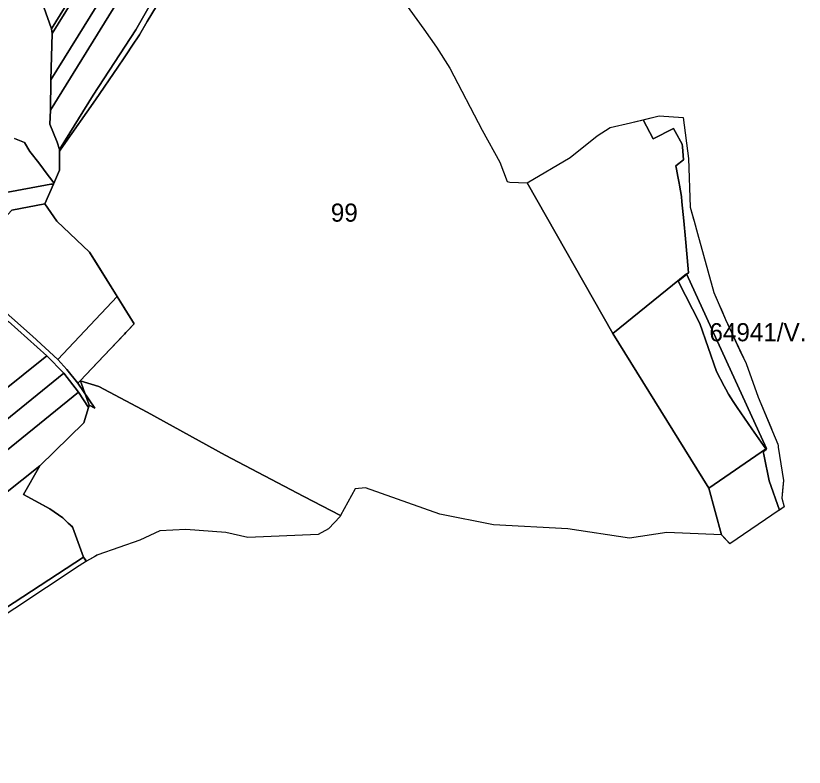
# Model space of a CAD drawing. Extents: x -521939 to -516426, y -1197857 to -1189551.
# Drawn here: x -517973 to -517320, y -1192725 to -1192103 of the extents above; entities that cross this region are included whole.
import ezdxf

# ---------------------------------------------------------------- set-up
doc = ezdxf.new("R2010")
doc.units = 0
for name, color, linetype in [('95610013', 7, 'Continuous'), ('95620013', 7, 'Continuous'), ('95640013', 7, 'Continuous'), ('95660013', 7, 'Continuous')]:
    doc.layers.add(name, color=color, linetype=linetype)

msp = doc.modelspace()

# ---------------------------------------------------------------- linework, layer by layer
at = {"layer": '95610013'}
for points in [[(-517855.24, -1191943.37), (-517837.87, -1191943.45), (-517848.22, -1191960.2), (-517943.23, -1192113.96), (-517949.43, -1192095.84)], [(-517944.02, -1192181.14), (-517850.97, -1192030.5), (-517797.36, -1191943.71), (-517762.7, -1191942.88), (-517770.79, -1191949.6), (-517801.09, -1191977.67), (-517817.56, -1192011.96), (-517823.62, -1192029.85), (-517844.83, -1192064.77), (-517873.31, -1192114.59), (-517908.65, -1192168.84), (-517936.59, -1192213.7), (-517938.51, -1192207.57), (-517944.58, -1192192.89)], [(-517797.36, -1191943.71), (-517850.97, -1192030.5), (-517944.02, -1192181.14), (-517943.62, -1192156.22), (-517849.72, -1192004.37), (-517812.16, -1191943.63)], [(-517834.43, -1191943.43), (-517812.16, -1191943.63), (-517849.72, -1192004.37), (-517943.62, -1192156.22), (-517942.72, -1192117.68), (-517847.17, -1191963.93)], [(-517943.23, -1192113.96), (-517848.22, -1191960.2), (-517837.87, -1191943.45), (-517834.43, -1191943.43), (-517847.17, -1191963.93), (-517942.72, -1192117.68)], [(-517888.81, -1192335.51), (-517938.01, -1192387.6), (-517958.84, -1192368.12), (-518010.6, -1192322.82), (-518012.03, -1192297.79), (-517998.31, -1192288.04), (-517976.01, -1192263.94), (-517948.58, -1192258.68), (-517938.71, -1192273.08), (-517911.8, -1192298.65)], [(-517938.01, -1192387.6), (-517888.81, -1192335.51), (-517874.81, -1192357.96), (-517919.33, -1192405.1), (-517921.42, -1192407.14), (-517930.4, -1192395.85)], [(-517979.17, -1192355.85), (-517947.12, -1192384.46), (-518062.13, -1192476.65), (-518198.61, -1192586.05), (-518210.9, -1192543.36), (-518070.51, -1192429.76)], [(-517947.12, -1192384.46), (-517933.09, -1192398.78), (-518052.55, -1192495.67), (-518192.07, -1192608.83), (-518198.61, -1192586.05), (-518062.13, -1192476.65)], [(-518192.07, -1192608.83), (-518052.55, -1192495.67), (-517933.09, -1192398.78), (-517920.9, -1192414.69), (-518047.2, -1192516.99), (-518186.13, -1192629.52)], [(-517920.9, -1192414.69), (-517912.56, -1192427.26), (-517916.41, -1192439.93), (-517952.89, -1192475.46), (-518042.44, -1192546.79), (-518178.78, -1192655.39), (-518186.13, -1192629.52), (-518047.2, -1192516.99)], [(-518178.78, -1192655.39), (-518042.44, -1192546.79), (-517952.89, -1192475.46), (-517966.33, -1192499.14), (-517944.59, -1192511.06), (-517933.87, -1192518.63), (-517925.61, -1192526.94), (-517916.64, -1192551.13), (-518003.1, -1192607.37), (-518073.65, -1192666.41), (-518085.13, -1192672.38), (-518111.4, -1192679.81), (-518157.63, -1192713.61), (-518162.65, -1192711.95)]]:
    msp.add_lwpolyline(points, close=True, dxfattribs=at)
at = {"layer": '95620013'}
msp.add_lwpolyline([(-517656.03, -1192084.87), (-517635, -1192114.23), (-517624.42, -1192129.01), (-517613.53, -1192146.34), (-517586.8, -1192197.68), (-517571.95, -1192224.17), (-517565.87, -1192240.11), (-517563.82, -1192240.76), (-517549.32, -1192241.33), (-517478.65, -1192365.95), (-517398.96, -1192494.02), (-517388.6, -1192532.69), (-517433.84, -1192530.84), (-517464.79, -1192535.46), (-517515.88, -1192527.65), (-517577.37, -1192524.4), (-517621.73, -1192515.48), (-517683.24, -1192493.66), (-517691.85, -1192494.5), (-517703.94, -1192516.77), (-517734.25, -1192500.81), (-517799.3, -1192466.75), (-517863.9, -1192431.15), (-517904.01, -1192409.83), (-517919.33, -1192405.1), (-517874.81, -1192357.96), (-517888.81, -1192335.51), (-517911.8, -1192298.65), (-517938.71, -1192273.08), (-517948.58, -1192258.68), (-517941.62, -1192242.33), (-517936.68, -1192230.73), (-517936.59, -1192213.7), (-517908.65, -1192168.84), (-517873.31, -1192114.59), (-517844.83, -1192064.77)], dxfattribs=at)
for points in [[(-517381.57, -1192539.95), (-517388.6, -1192532.69), (-517398.96, -1192494.02), (-517351.35, -1192461.17), (-517417.53, -1192316.62), (-517478.65, -1192365.95), (-517549.32, -1192241.33), (-517513.77, -1192220.34), (-517491.36, -1192202.35), (-517480.7, -1192195.55), (-517463.82, -1192191.59), (-517440.05, -1192185.9), (-517420.36, -1192187.14), (-517415.92, -1192221.1), (-517414.44, -1192261.44), (-517411.2, -1192273.11), (-517408.37, -1192283.3), (-517394.85, -1192332.07), (-517385.15, -1192354.39), (-517368.25, -1192390.88), (-517358.3, -1192418.72), (-517346.37, -1192447.19), (-517342.01, -1192457.6), (-517341.78, -1192459.09), (-517341.63, -1192460.06), (-517337.35, -1192487.59), (-517338.56, -1192502.18), (-517336.77, -1192509.6), (-517340.8, -1192512.33)], [(-517351.35, -1192461.17), (-517398.96, -1192494.02), (-517478.65, -1192365.95), (-517417.53, -1192316.62)], [(-517780.59, -1192534.85), (-517798.9, -1192530.79), (-517831.88, -1192528.24), (-517853.37, -1192529.23), (-517870.09, -1192537.11), (-517904.9, -1192549.16), (-517914.33, -1192554.36), (-517916.64, -1192551.13), (-517925.61, -1192526.94), (-517933.87, -1192518.63), (-517944.59, -1192511.06), (-517966.33, -1192499.14), (-517952.89, -1192475.46), (-517916.41, -1192439.93), (-517912.56, -1192427.26), (-517911.95, -1192425.26), (-517907.44, -1192427.78), (-517921.42, -1192407.14), (-517919.33, -1192405.1), (-517904.01, -1192409.83), (-517863.9, -1192431.15), (-517799.3, -1192466.75), (-517734.25, -1192500.81), (-517703.94, -1192516.77), (-517704.26, -1192517.36), (-517713.94, -1192527.65), (-517722.38, -1192532.36)]]:
    msp.add_lwpolyline(points, close=True, dxfattribs=at)
at = {"layer": '95640013'}
for points in [[(-517949.43, -1192095.84), (-517943.23, -1192113.96), (-517942.72, -1192117.68), (-517943.62, -1192156.22), (-517944.02, -1192181.14), (-517944.58, -1192192.89), (-517938.51, -1192207.57), (-517936.59, -1192213.7), (-517936.68, -1192230.73), (-517941.62, -1192242.33), (-517943.65, -1192242.55), (-517983.84, -1192249.8)], [(-517983.84, -1192249.8), (-517943.65, -1192242.55), (-517941.62, -1192242.33), (-517948.58, -1192258.68), (-517976.01, -1192263.94)], [(-518010.6, -1192322.82), (-517958.84, -1192368.12), (-517938.01, -1192387.6), (-517930.4, -1192395.85), (-517921.42, -1192407.14), (-517907.44, -1192427.78), (-517911.95, -1192425.26), (-517912.56, -1192427.26), (-517920.9, -1192414.69), (-517933.09, -1192398.78), (-517947.12, -1192384.46), (-517979.17, -1192355.85)]]:
    msp.add_lwpolyline(points, dxfattribs=at)
msp.add_lwpolyline([(-517914.33, -1192554.36), (-517920.39, -1192558.37), (-518000.71, -1192611.51), (-518044.98, -1192646.87), (-518100.15, -1192695.18), (-518106.7, -1192687.4), (-518113.39, -1192685.66), (-518137.16, -1192707.07), (-518143.03, -1192712.13), (-518149.04, -1192717.31), (-518158.94, -1192724.96), (-518162.65, -1192711.95), (-518157.63, -1192713.61), (-518111.4, -1192679.81), (-518085.13, -1192672.38), (-518073.65, -1192666.41), (-518003.1, -1192607.37), (-517916.64, -1192551.13)], close=True, dxfattribs=at)
at = {"layer": '95660013'}
for points in [[(-517852.5, -1192088.57), (-517863.87, -1192107.85), (-517870.31, -1192118.76), (-517872.65, -1192122.28), (-517874.38, -1192124.89), (-517882.99, -1192137.84), (-517888.28, -1192145.57), (-517906.87, -1192172.76), (-517933.46, -1192210.67), (-517936.6, -1192215.11), (-517936.59, -1192213.7), (-517938.51, -1192207.57), (-517944.58, -1192192.89), (-517944.02, -1192181.14), (-517943.62, -1192156.22), (-517942.72, -1192117.68), (-517943.23, -1192113.96), (-517949.43, -1192095.84)], [(-517949.43, -1192095.84), (-517943.23, -1192113.96), (-517942.72, -1192117.68), (-517943.62, -1192156.22), (-517944.02, -1192181.14), (-517944.58, -1192192.89), (-517938.51, -1192207.57), (-517936.59, -1192213.7), (-517936.6, -1192215.11), (-517933.46, -1192210.67), (-517906.87, -1192172.76), (-517888.28, -1192145.57), (-517882.99, -1192137.84), (-517874.38, -1192124.89), (-517872.65, -1192122.28), (-517870.31, -1192118.76), (-517863.87, -1192107.85), (-517852.5, -1192088.57)], [(-517656.03, -1192084.87), (-517635, -1192114.23), (-517624.42, -1192129.01), (-517613.53, -1192146.34), (-517586.8, -1192197.68), (-517571.95, -1192224.17), (-517565.87, -1192240.11), (-517563.82, -1192240.76), (-517549.32, -1192241.33), (-517513.77, -1192220.34), (-517491.36, -1192202.35), (-517480.7, -1192195.55), (-517463.82, -1192191.59), (-517453.49, -1192189.12), (-517445.17, -1192205.02), (-517428.37, -1192196.33), (-517427.02, -1192198.77), (-517421.17, -1192209.36), (-517420.95, -1192211.66), (-517419.93, -1192222.33), (-517426.31, -1192227.14), (-517426.03, -1192228.72), (-517425.82, -1192229.88), (-517424.67, -1192236.16), (-517423.67, -1192241.61), (-517423.4, -1192243.12), (-517421.68, -1192252.53), (-517421.26, -1192256.95), (-517419.78, -1192272.72), (-517418.39, -1192287.56), (-517416.17, -1192312.44), (-517415.87, -1192315.79), (-517416.88, -1192316.62), (-517417.35, -1192317.01), (-517424.38, -1192322.83), (-517406.6, -1192357.69), (-517392.72, -1192397.57), (-517386.27, -1192409.69), (-517384.93, -1192412.19), (-517382.77, -1192416.26), (-517378.9, -1192422.25), (-517375.55, -1192427.17), (-517363.46, -1192444.96), (-517351.88, -1192461.54), (-517351.49, -1192462.1), (-517352.97, -1192463.09), (-517353.65, -1192463.55), (-517354.01, -1192463.8), (-517353.26, -1192467.57), (-517349.2, -1192487.92), (-517340.49, -1192512.12), (-517340.8, -1192512.33), (-517381.57, -1192539.95), (-517381.79, -1192539.72), (-517388.6, -1192532.69), (-517433.84, -1192530.84), (-517464.79, -1192535.46), (-517515.88, -1192527.65), (-517577.37, -1192524.4), (-517621.73, -1192515.48), (-517683.24, -1192493.66), (-517691.85, -1192494.5), (-517703.94, -1192516.77), (-517704.26, -1192517.36), (-517713.94, -1192527.65), (-517722.38, -1192532.36), (-517780.59, -1192534.85), (-517798.9, -1192530.79), (-517831.88, -1192528.24), (-517853.37, -1192529.23), (-517870.09, -1192537.11)], [(-517337.35, -1192487.59), (-517338.01, -1192495.54), (-517338.56, -1192502.18), (-517336.77, -1192509.6), (-517340.49, -1192512.12), (-517349.2, -1192487.92), (-517353.26, -1192467.57), (-517354.01, -1192463.8), (-517353.65, -1192463.55), (-517352.97, -1192463.09), (-517351.49, -1192462.1), (-517351.88, -1192461.54), (-517363.46, -1192444.96), (-517375.55, -1192427.17), (-517378.9, -1192422.25), (-517382.77, -1192416.26), (-517384.93, -1192412.19), (-517386.27, -1192409.69), (-517392.72, -1192397.57), (-517406.6, -1192357.69), (-517424.38, -1192322.83), (-517417.35, -1192317.01), (-517416.88, -1192316.62), (-517415.87, -1192315.79), (-517416.17, -1192312.44), (-517418.39, -1192287.56), (-517419.78, -1192272.72), (-517421.26, -1192256.95), (-517421.68, -1192252.53), (-517423.4, -1192243.12), (-517423.67, -1192241.61), (-517424.67, -1192236.16), (-517425.82, -1192229.88), (-517426.03, -1192228.72), (-517426.31, -1192227.14), (-517419.93, -1192222.33), (-517420.95, -1192211.66), (-517421.17, -1192209.36), (-517427.02, -1192198.77), (-517428.37, -1192196.33), (-517445.17, -1192205.02), (-517453.49, -1192189.12), (-517440.05, -1192185.9), (-517420.36, -1192187.14), (-517415.92, -1192221.1), (-517414.44, -1192261.44), (-517411.67, -1192271.43), (-517411.2, -1192273.11), (-517408.37, -1192283.3), (-517394.85, -1192332.07), (-517389.28, -1192344.9), (-517389.27, -1192344.91), (-517389.21, -1192345.06), (-517385.15, -1192354.39), (-517373.81, -1192378.88), (-517373.54, -1192379.46), (-517370.03, -1192387.04), (-517368.25, -1192390.88), (-517358.3, -1192418.72), (-517347.86, -1192443.64), (-517346.37, -1192447.19), (-517342.01, -1192457.6), (-517341.78, -1192459.09), (-517341.63, -1192460.06), (-517337.35, -1192487.59)], [(-517973.73, -1192204.51), (-517965.64, -1192208), (-517960.99, -1192215.3), (-517953.72, -1192224.84), (-517949.7, -1192230.11), (-517948.4, -1192231.82), (-517941.18, -1192241.29), (-517941.62, -1192242.33), (-517948.58, -1192258.68), (-517938.71, -1192273.08), (-517911.8, -1192298.65), (-517906.03, -1192307.91), (-517888.81, -1192335.51), (-517880.87, -1192348.24), (-517874.81, -1192357.96), (-517881.55, -1192365.1), (-517882.81, -1192366.43), (-517905.05, -1192389.98), (-517919.33, -1192405.1), (-517918.71, -1192406.8), (-517915.25, -1192416.25), (-517913.98, -1192419.71), (-517911.95, -1192425.26), (-517912.27, -1192426.33), (-517912.55, -1192427.26), (-517916.41, -1192439.93), (-517952.89, -1192475.46), (-517966.33, -1192499.14), (-517950.03, -1192508.08), (-517944.59, -1192511.06), (-517933.87, -1192518.63), (-517929.35, -1192522.85), (-517925.92, -1192526.05), (-517925.61, -1192526.93), (-517916.65, -1192551.11), (-517914.52, -1192554.48), (-517914.33, -1192554.36), (-517920.39, -1192558.37), (-518000.71, -1192611.51)], [(-517870.09, -1192537.11), (-517904.74, -1192549.1), (-517904.9, -1192549.16), (-517905.54, -1192549.51), (-517908.23, -1192550.99), (-517914.33, -1192554.36), (-517914.52, -1192554.48), (-517916.65, -1192551.11), (-517925.61, -1192526.93), (-517925.92, -1192526.05), (-517929.35, -1192522.85), (-517933.87, -1192518.63), (-517944.59, -1192511.06), (-517950.03, -1192508.08), (-517966.33, -1192499.14), (-517952.89, -1192475.46), (-517916.41, -1192439.93), (-517912.55, -1192427.26), (-517912.27, -1192426.33), (-517911.95, -1192425.26), (-517913.98, -1192419.71), (-517915.25, -1192416.25), (-517918.71, -1192406.8), (-517919.33, -1192405.1), (-517905.05, -1192389.98), (-517882.81, -1192366.43), (-517881.55, -1192365.1), (-517874.81, -1192357.96), (-517880.87, -1192348.24), (-517888.81, -1192335.51), (-517906.03, -1192307.91), (-517911.8, -1192298.65), (-517938.71, -1192273.08), (-517948.58, -1192258.68), (-517941.62, -1192242.33), (-517941.18, -1192241.29), (-517948.4, -1192231.82), (-517949.7, -1192230.11), (-517953.72, -1192224.84), (-517960.99, -1192215.3), (-517965.64, -1192208), (-517973.73, -1192204.51)]]:
    msp.add_lwpolyline(points, dxfattribs=at)

# ---------------------------------------------------------------- texts
for s, p in [('99', (-517711.94, -1192273.48)), ('64941/V.', (-517398.55, -1192372.45))]:
    msp.add_text(s, height=15, rotation=0, dxfattribs=at).set_placement(p)

doc.saveas('drawing.dxf')
